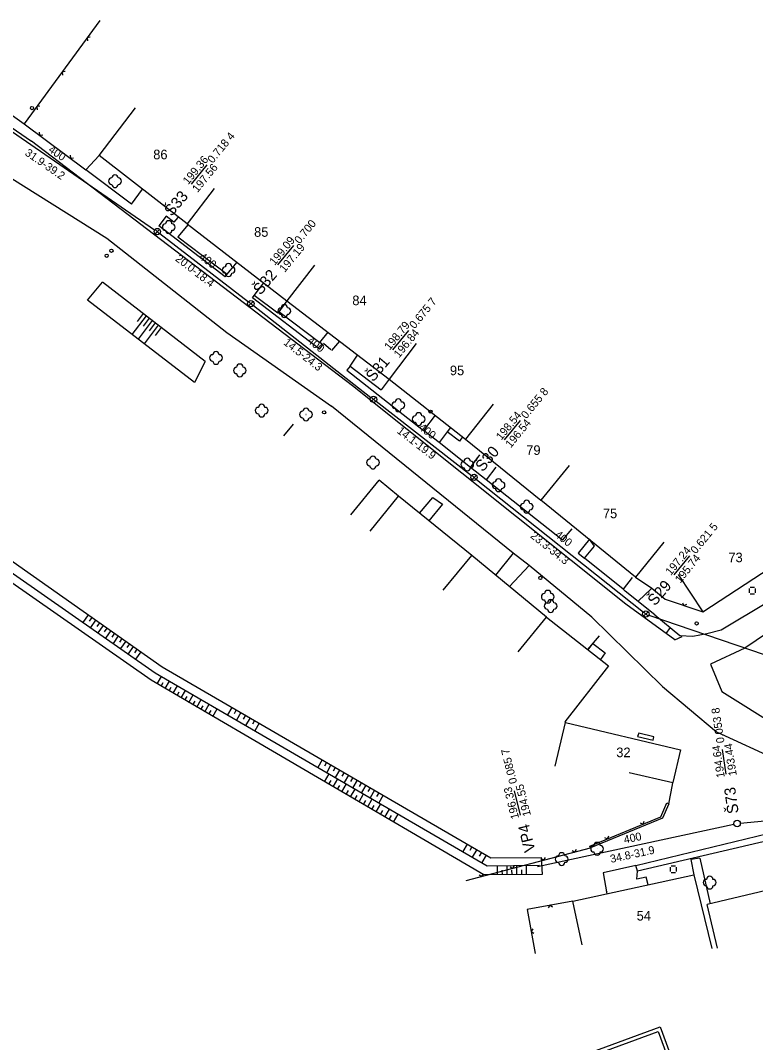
# Model space of a CAD drawing. Extents: x -574526 to -573537, y -1188297 to -1187280.
# Drawn here: x -574158.2 to -574043.3, y -1188086.8 to -1187927.2 of the extents above; entities that cross this region are included whole.
import ezdxf

# ---------------------------------------------------------------- set-up
doc = ezdxf.new("R2010")
doc.units = 0
for name, color, linetype in [('Vrstva 10', 7, 'Continuous'), ('Vrstva 12', 7, 'Continuous'), ('Vrstva 13', 7, 'Continuous'), ('Vrstva 14', 7, 'Continuous'), ('Vrstva 17', 7, 'Continuous'), ('Vrstva 18', 7, 'Continuous'), ('Vrstva 2', 7, 'Continuous'), ('Vrstva 21', 7, 'Continuous'), ('Vrstva 4', 7, 'Continuous'), ('Vrstva 41', 7, 'Continuous'), ('Vrstva 6', 7, 'Continuous'), ('Vrstva 7', 7, 'Continuous'), ('Vrstva 8', 7, 'Continuous'), ('Vrstva 9', 7, 'Continuous')]:
    doc.layers.add(name, color=color, linetype=linetype)

# ---------------------------------------------------------------- blocks, each defined once
blk = doc.blocks.new('3$130')
at = {"layer": 'Vrstva 8'}
blk.add_circle((0, 0), 0.001, dxfattribs=at)
for centre, start, end in [((-1, 0), 90, 270), ((0, 1), 0, 180), ((1, 0), 270, 90), ((0, -1), 180, 0)]:
    blk.add_arc(centre, 1, start, end, dxfattribs=at)
blk = doc.blocks.new('6$010')
at = {"layer": 'Vrstva 21'}
blk.add_circle((0, 0), 0.5, dxfattribs=at)
blk = doc.blocks.new('6$091')
at = {"layer": 'Vrstva 21'}
for p, q in [((-1, 0.7), (-1, -0.7)), ((0.7, 1), (-0.7, 1)), ((1, -0.7), (1, 0.7)), ((-0.7, -1), (0.7, -1))]:
    blk.add_line(p, q, dxfattribs=at)

msp = doc.modelspace()

# ---------------------------------------------------------------- linework, layer by layer
at = {"layer": 'Vrstva 10'}
for p, q in [((-574147.72, -1187970.91), (-574145.39, -1187968.11)), ((-574129.33, -1187980.45), (-574145.39, -1187968.11)), ((-574131.03, -1187983.73), (-574147.72, -1187970.91)), ((-574139.04, -1187972.99), (-574139.99, -1187974.22)), ((-574138.56, -1187973.35), (-574140.78, -1187976.24)), ((-574137.61, -1187974.09), (-574139.83, -1187976.97)), ((-574138.09, -1187973.72), (-574139.03, -1187974.95)), ((-574137.14, -1187974.45), (-574138.08, -1187975.68)), ((-574136.66, -1187974.82), (-574138.88, -1187977.7)), ((-574136.19, -1187975.18), (-574137.13, -1187976.41)), ((-574129.33, -1187980.45), (-574131.03, -1187983.73)), ((-574147.62, -1188020.02), (-574148.45, -1188021.21)), ((-574147.04, -1188020.44), (-574147.45, -1188021.03)), ((-574146.45, -1188020.85), (-574147.27, -1188022.03)), ((-574145.86, -1188021.26), (-574146.27, -1188021.85)), ((-574145.28, -1188021.68), (-574146.1, -1188022.85)), ((-574144.69, -1188022.09), (-574145.1, -1188022.68)), ((-574144.1, -1188022.5), (-574144.92, -1188023.67)), ((-574143.52, -1188022.92), (-574143.92, -1188023.5)), ((-574142.93, -1188023.33), (-574143.74, -1188024.49)), ((-574142.34, -1188023.74), (-574142.75, -1188024.32)), ((-574141.76, -1188024.16), (-574142.57, -1188025.31)), ((-574141.17, -1188024.57), (-574141.57, -1188025.15)), ((-574140.58, -1188024.98), (-574141.39, -1188026.14)), ((-574140, -1188025.39), (-574140.4, -1188025.97)), ((-574139.41, -1188025.81), (-574140.21, -1188026.96)), ((-574136.84, -1188030.82), (-574136.17, -1188029.66)), ((-574136.22, -1188031.18), (-574135.88, -1188030.6)), ((-574135.6, -1188031.55), (-574134.92, -1188030.38)), ((-574134.98, -1188031.91), (-574134.64, -1188031.33)), ((-574134.36, -1188032.27), (-574133.68, -1188031.11)), ((-574133.73, -1188032.64), (-574133.39, -1188032.05)), ((-574133.11, -1188033), (-574132.43, -1188031.83)), ((-574132.49, -1188033.36), (-574132.15, -1188032.78)), ((-574131.87, -1188033.73), (-574131.19, -1188032.55)), ((-574131.25, -1188034.09), (-574130.9, -1188033.5)), ((-574130.62, -1188034.45), (-574129.94, -1188033.28)), ((-574130, -1188034.82), (-574129.66, -1188034.23)), ((-574129.38, -1188035.18), (-574128.69, -1188034)), ((-574128.76, -1188035.54), (-574128.41, -1188034.95)), ((-574128.14, -1188035.91), (-574127.45, -1188034.72)), ((-574125.19, -1188034.48), (-574125.86, -1188035.64)), ((-574124.47, -1188034.89), (-574124.81, -1188035.48)), ((-574123.76, -1188035.31), (-574124.44, -1188036.47)), ((-574123.05, -1188035.72), (-574123.38, -1188036.3)), ((-574122.33, -1188036.14), (-574123.01, -1188037.3)), ((-574121.62, -1188036.55), (-574121.96, -1188037.13)), ((-574120.91, -1188036.97), (-574121.58, -1188038.13)), ((-574111.04, -1188042.69), (-574111.71, -1188043.86)), ((-574110.36, -1188043.09), (-574110.7, -1188043.67)), ((-574110.67, -1188046.1), (-574109.96, -1188044.88)), ((-574109.68, -1188043.48), (-574110.35, -1188044.65)), ((-574109, -1188043.88), (-574109.34, -1188044.46)), ((-574108.32, -1188044.27), (-574109, -1188045.44)), ((-574107.64, -1188044.67), (-574107.98, -1188045.25)), ((-574110, -1188046.5), (-574109.64, -1188045.88)), ((-574109.33, -1188046.89), (-574108.61, -1188045.66)), ((-574107.98, -1188047.68), (-574107.26, -1188046.44)), ((-574106.96, -1188045.06), (-574107.64, -1188046.22)), ((-574106.28, -1188045.45), (-574106.62, -1188046.04)), ((-574105.61, -1188045.85), (-574106.28, -1188047.01)), ((-574104.93, -1188046.24), (-574105.26, -1188046.82)), ((-574108.65, -1188047.28), (-574108.3, -1188046.67)), ((-574107.31, -1188048.07), (-574106.95, -1188047.45)), ((-574106.63, -1188048.46), (-574105.92, -1188047.23)), ((-574105.29, -1188049.25), (-574104.57, -1188048.01)), ((-574104.25, -1188046.64), (-574104.92, -1188047.8)), ((-574103.57, -1188047.03), (-574103.91, -1188047.61)), ((-574102.89, -1188047.42), (-574103.57, -1188048.59)), ((-574102.21, -1188047.82), (-574102.55, -1188048.4)), ((-574105.96, -1188048.86), (-574105.6, -1188048.24)), ((-574104.61, -1188049.64), (-574104.25, -1188049.02)), ((-574103.94, -1188050.03), (-574103.22, -1188048.79)), ((-574102.59, -1188050.82), (-574101.87, -1188049.57)), ((-574101.53, -1188048.21), (-574102.21, -1188049.38)), ((-574103.27, -1188050.43), (-574102.91, -1188049.81)), ((-574101.92, -1188051.21), (-574101.56, -1188050.59)), ((-574101.25, -1188051.61), (-574100.52, -1188050.36)), ((-574099.9, -1188052.39), (-574099.17, -1188051.14)), ((-574100.57, -1188052), (-574100.21, -1188051.37)), ((-574088.4, -1188055.84), (-574089.08, -1188057)), ((-574087.65, -1188056.27), (-574087.99, -1188056.85)), ((-574086.91, -1188056.7), (-574087.59, -1188057.87)), ((-574086.16, -1188057.13), (-574086.5, -1188057.72)), ((-574085.42, -1188057.57), (-574086.1, -1188058.73)), ((-574083.65, -1188060.61), (-574083.67, -1188059.21)), ((-574082.13, -1188060.6), (-574082.15, -1188059.18)), ((-574080.62, -1188060.6), (-574080.64, -1188059.16)), ((-574079.11, -1188060.59), (-574079.13, -1188059.14)), ((-574076.85, -1188057.9), (-574076.68, -1188060.58)), ((-574082.89, -1188060.61), (-574082.9, -1188059.9)), ((-574081.38, -1188060.6), (-574081.39, -1188059.89)), ((-574079.86, -1188060.59), (-574079.87, -1188059.87))]:
    msp.add_line(p, q, dxfattribs=at)
for points in [[(-574317.29, -1188004.39), (-574314.14, -1188013.05), (-574301.75, -1188030.62), (-574291.92, -1188042.55), (-574288.38, -1188041.78), (-574266.39, -1188025.47), (-574244.62, -1188011.25), (-574215.09, -1187994.87), (-574205.35, -1187992.52), (-574193.85, -1187992.52), (-574182.59, -1187996.03), (-574179.48, -1187997.59), (-574136.05, -1188028.17), (-574084.72, -1188057.97), (-574076.85, -1188057.9)], [(-574076.68, -1188060.58), (-574085.81, -1188060.62), (-574137.8, -1188030.26), (-574182.44, -1187999.09), (-574194.25, -1187995.12), (-574205.38, -1187995.31), (-574213.71, -1187997.65), (-574242.91, -1188013.72), (-574264.49, -1188027.8), (-574277.96, -1188037.93), (-574288.47, -1188045), (-574293.01, -1188045.4), (-574304.15, -1188032.01), (-574316.54, -1188013.81), (-574318.99, -1188004.72)], [(-574318.14, -1188004.55), (-574315.35, -1188013.5), (-574302.73, -1188031.74), (-574292.54, -1188043.84), (-574288.81, -1188043.39), (-574285.58, -1188041.49), (-574264.64, -1188026.29), (-574243.98, -1188012.52), (-574214.39, -1187996.33), (-574205.28, -1187993.91), (-574194.11, -1187993.91), (-574181.46, -1187998.19), (-574137.17, -1188029.08), (-574085.25, -1188059.23), (-574077.09, -1188059.12)]]:
    msp.add_lwpolyline(points, dxfattribs=at)
at = {"layer": 'Vrstva 13'}
for p, q in [((-574131.49, -1187952.81), (-574129.01, -1187949.79)), ((-574117.96, -1187965.4), (-574115.49, -1187962.38)), ((-574100, -1187978.65), (-574097.52, -1187975.64)), ((-574082.55, -1187992.71), (-574080.07, -1187989.69)), ((-574056.06, -1188013.81), (-574053.58, -1188010.8)), ((-574047.91, -1188044.92), (-574048.5, -1188041.06)), ((-574080.08, -1188051.29), (-574081.02, -1188047.5))]:
    msp.add_line(p, q, dxfattribs=at)
at = {"layer": 'Vrstva 17'}
for p, q in [((-574137.17, -1187960.55), (-574136.46, -1187959.84)), ((-574137.17, -1187959.84), (-574136.46, -1187960.55)), ((-574122.55, -1187971.8), (-574121.84, -1187971.09)), ((-574122.55, -1187971.09), (-574121.84, -1187971.8)), ((-574103.39, -1187986.74), (-574102.68, -1187986.03)), ((-574103.39, -1187986.03), (-574102.68, -1187986.74)), ((-574087.67, -1187998.93), (-574086.96, -1187998.22)), ((-574087.67, -1187998.22), (-574086.96, -1187998.93)), ((-574060.82, -1188020.26), (-574060.11, -1188019.56)), ((-574060.82, -1188019.56), (-574060.11, -1188020.26))]:
    msp.add_line(p, q, dxfattribs=at)
at = {"layer": 'Vrstva 2'}
for p, q in [((-574168.68, -1187938.27), (-574137.23, -1187959.91)), ((-574136.42, -1187960.5), (-574122.59, -1187971.14)), ((-574121.8, -1187971.75), (-574103.43, -1187986.08)), ((-574102.64, -1187986.69), (-574087.71, -1187998.27)), ((-574086.93, -1187998.89), (-574060.86, -1188019.6)), ((-574059.99, -1188020.07), (-573995.71, -1188042.01)), ((-574045.71, -1188052.57), (-574001.26, -1188048.17)), ((-574077.38, -1188059.33), (-574046.7, -1188052.73))]:
    msp.add_line(p, q, dxfattribs=at)
at = {"layer": 'Vrstva 41'}
for points in [[(-574145.41, -1188116.41), (-574058.21, -1188084.39), (-574036.76, -1188142.83), (-574123.95, -1188174.84), (-574145.41, -1188116.41)], [(-574144.69, -1188116.76), (-574058.53, -1188085.12), (-574037.46, -1188142.5), (-574123.63, -1188174.14), (-574144.69, -1188116.76)]]:
    msp.add_lwpolyline(points, close=True, dxfattribs=at)
at = {"layer": 'Vrstva 6'}
for p, q in [((-574145.81, -1187927.22), (-574157.62, -1187943.36)), ((-574157.62, -1187943.36), (-574147.98, -1187950.54)), ((-574147.98, -1187950.54), (-574145.91, -1187948.33)), ((-574131.97, -1187959.09), (-574133.6, -1187961)), ((-574133.6, -1187961), (-574125.9, -1187966.86)), ((-574125.9, -1187966.86), (-574124.34, -1187964.98)), ((-574121.66, -1187970.17), (-574120.16, -1187968.2)), ((-574118, -1187972.95), (-574121.66, -1187970.17)), ((-574116.55, -1187970.99), (-574118, -1187972.95)), ((-574117.83, -1187972.65), (-574111.43, -1187977.52)), ((-574111.43, -1187977.52), (-574110.13, -1187975.91)), ((-574110.93, -1187977.85), (-574111.43, -1187977.52)), ((-574109.56, -1187978.76), (-574108.29, -1187977.32)), ((-574106.66, -1187981.23), (-574105.54, -1187979.51)), ((-574106.66, -1187981.23), (-574101.81, -1187984.92)), ((-574100.6, -1187983.21), (-574101.81, -1187984.92)), ((-574062.08, -1188014.13), (-574059.55, -1188015.88)), ((-574061.6, -1188017.83), (-574059.67, -1188016.05)), ((-574059.67, -1188016.05), (-574059.55, -1188015.88)), ((-574059.55, -1188015.88), (-574057.44, -1188017.61)), ((-574057.44, -1188017.61), (-574051.58, -1188019.59)), ((-574048.71, -1188022.38), (-574041.33, -1188017.96)), ((-574050.93, -1188022.95), (-574048.71, -1188022.38)), ((-574069.55, -1188025.45), (-574067.74, -1188023.32)), ((-574055.15, -1188023.24), (-574053.11, -1188023.37)), ((-574053.11, -1188023.37), (-574050.93, -1188022.95)), ((-574069.48, -1188025.51), (-574068.75, -1188024.52)), ((-574068.75, -1188024.52), (-574066.81, -1188025.96)), ((-574066.81, -1188025.96), (-574067.56, -1188027.02)), ((-574061.58, -1188038.53), (-574061.76, -1188039.04)), ((-574059.21, -1188039.07), (-574061.58, -1188038.53)), ((-574061.76, -1188039.04), (-574059.33, -1188039.59)), ((-574059.33, -1188039.59), (-574059.21, -1188039.07)), ((-574056.31, -1188046.58), (-574056.25, -1188046.23)), ((-574056.9, -1188049.52), (-574056.31, -1188046.58)), ((-574058.12, -1188051.57), (-574057.17, -1188049.4)), ((-574056.9, -1188049.52), (-574057.89, -1188051.8)), ((-574057.17, -1188049.4), (-574056.9, -1188049.52)), ((-574069.24, -1188056.16), (-574058.12, -1188051.57)), ((-574057.89, -1188051.8), (-574069.13, -1188056.44)), ((-574088.53, -1188061.53), (-574069.13, -1188056.44)), ((-574069.13, -1188056.44), (-574069.24, -1188056.16)), ((-574071.9, -1188064.73), (-574079.03, -1188066.03)), ((-574079.03, -1188066.03), (-574077.78, -1188072.91))]:
    msp.add_line(p, q, dxfattribs=at)
for points in [[(-574147.29, -1187929.83), (-574147.78, -1187929.91), (-574147.7, -1187930.4)], [(-574151.23, -1187935.21), (-574151.71, -1187935.29), (-574151.64, -1187935.78)], [(-574155.16, -1187940.59), (-574155.65, -1187940.67), (-574155.58, -1187941.16)], [(-574155.28, -1187944.67), (-574155.21, -1187945.16), (-574154.72, -1187945.08)], [(-574150.46, -1187948.26), (-574150.39, -1187948.75), (-574149.9, -1187948.67)], [(-574054.73, -1188018.16), (-574054.51, -1188018.6), (-574054.07, -1188018.38)], [(-574061.36, -1188052.53), (-574060.9, -1188052.72), (-574060.71, -1188052.26)], [(-574066.92, -1188054.82), (-574066.46, -1188055.01), (-574066.27, -1188054.56)], [(-574071.98, -1188056.83), (-574071.56, -1188057.08), (-574071.31, -1188056.65)], [(-574081.68, -1188059.37), (-574081.26, -1188059.62), (-574081.01, -1188059.19)], [(-574076.83, -1188058.1), (-574076.41, -1188058.35), (-574076.16, -1188057.92)], [(-574086.53, -1188060.64), (-574086.1, -1188060.89), (-574085.86, -1188060.47)], [(-574075.06, -1188065.66), (-574075.47, -1188065.38), (-574075.75, -1188065.78)], [(-574078.12, -1188069.06), (-574078.41, -1188069.47), (-574078, -1188069.75)]]:
    msp.add_lwpolyline(points, dxfattribs=at)
at = {"layer": 'Vrstva 7'}
for p, q in [((-574145.91, -1187948.33), (-574140.25, -1187940.89)), ((-574132.17, -1187958.99), (-574145.91, -1187948.33)), ((-574127.91, -1187953.44), (-574132.17, -1187958.99)), ((-574132.17, -1187958.99), (-574116.55, -1187970.99)), ((-574112.27, -1187965.45), (-574116.55, -1187970.99)), ((-574116.55, -1187970.99), (-574100.6, -1187983.21)), ((-574096.34, -1187977.65), (-574100.6, -1187983.21)), ((-574100.6, -1187983.21), (-574088.64, -1187992.62)), ((-574084.31, -1187987.12), (-574088.64, -1187992.62)), ((-574117.04, -1187992.1), (-574115.51, -1187990.24)), ((-574088.64, -1187992.62), (-574076.86, -1188002.14)), ((-574072.46, -1187996.7), (-574076.86, -1188002.14)), ((-574106.6, -1188004.43), (-574102.15, -1187999.03)), ((-574099.13, -1188001.52), (-574102.15, -1187999.03)), ((-574103.53, -1188006.97), (-574099.13, -1188001.52)), ((-574087.68, -1188010.76), (-574099.13, -1188001.52)), ((-574062.08, -1188014.13), (-574076.86, -1188002.14)), ((-574057.67, -1188008.69), (-574062.08, -1188014.13)), ((-574092.13, -1188016.17), (-574087.68, -1188010.76)), ((-574075.99, -1188020.38), (-574087.68, -1188010.76)), ((-574051.58, -1188019.59), (-574038.35, -1188010.94)), ((-574055.41, -1188013.73), (-574051.58, -1188019.59)), ((-574080.44, -1188025.79), (-574075.99, -1188020.38)), ((-574075.99, -1188020.38), (-574066.3, -1188028.01)), ((-574066.3, -1188028.01), (-574073.15, -1188036.73)), ((-574074.62, -1188043.67), (-574073.01, -1188036.86)), ((-574073.15, -1188036.73), (-574073.01, -1188036.86)), ((-574073.01, -1188036.86), (-574055.07, -1188041.09)), ((-574055.07, -1188041.09), (-574056.25, -1188046.23)), ((-574063.07, -1188044.66), (-574056.25, -1188046.23)), ((-574056.25, -1188046.23), (-574056.22, -1188046.1)), ((-574071.9, -1188064.73), (-574052.98, -1188060.65)), ((-574052.98, -1188060.65), (-574050.17, -1188072.11)), ((-574030.86, -1188060.49), (-574050.87, -1188065.26)), ((-574070.42, -1188071.57), (-574071.9, -1188064.73)), ((-574049.25, -1188072.07), (-574050.87, -1188065.26))]:
    msp.add_line(p, q, dxfattribs=at)
at = {"layer": 'Vrstva 8'}
for centre in [(-574136.82, -1187960.19), (-574122.2, -1187971.44), (-574103.03, -1187986.39), (-574087.32, -1187998.57), (-574060.47, -1188019.91), (-574046.21, -1188052.62)]:
    msp.add_circle(centre, 0.5, dxfattribs=at)
at = {"layer": 'Vrstva 9'}
for p, q in [((-574179.15, -1187939.7), (-574144.7, -1187961.2)), ((-574106.32, -1187984.27), (-574156.49, -1187946.06)), ((-574140.84, -1187955.89), (-574147.98, -1187950.54)), ((-574140.84, -1187955.89), (-574139.14, -1187953.58)), ((-574135.43, -1187957.8), (-574136.57, -1187959.27)), ((-574134.25, -1187958.74), (-574135.43, -1187957.8)), ((-574133.62, -1187957.97), (-574134.25, -1187958.74)), ((-574126.2, -1187967.25), (-574136.57, -1187959.27)), ((-574144.7, -1187961.2), (-574125.95, -1187975.97)), ((-574126.2, -1187967.25), (-574125.9, -1187966.86)), ((-574121.93, -1187970.53), (-574121.66, -1187970.17)), ((-574111.49, -1187978.55), (-574121.93, -1187970.53)), ((-574125.95, -1187975.97), (-574109.61, -1187987.44)), ((-574111.49, -1187978.55), (-574110.93, -1187977.85)), ((-574109.71, -1187978.63), (-574110.82, -1187977.68)), ((-574106.66, -1187981.23), (-574107.2, -1187981.81)), ((-574107.2, -1187981.81), (-574095.23, -1187991.23)), ((-574063.62, -1188018.37), (-574106.32, -1187984.27)), ((-574081.22, -1188010.4), (-574109.61, -1187987.44)), ((-574093.42, -1187988.86), (-574095.23, -1187991.23)), ((-574092.77, -1187993.11), (-574095.23, -1187991.23)), ((-574091.52, -1187991.48), (-574092.77, -1187993.11)), ((-574090.99, -1187990.77), (-574091.52, -1187991.48)), ((-574089.6, -1187992.92), (-574091.52, -1187991.48)), ((-574089.1, -1187992.26), (-574089.6, -1187992.92)), ((-574087.88, -1187997.01), (-574092.77, -1187993.11)), ((-574087.88, -1187997.01), (-574086.43, -1187995.07)), ((-574085.44, -1187998.97), (-574087.88, -1187997.01)), ((-574083.93, -1187996.98), (-574085.44, -1187998.97)), ((-574073.49, -1188008.37), (-574085.44, -1187998.97)), ((-574095.85, -1188004.17), (-574093.74, -1188001.71)), ((-574093.74, -1188001.71), (-574092.24, -1188002.76)), ((-574092.24, -1188002.76), (-574094.4, -1188005.33)), ((-574073.49, -1188008.37), (-574071.99, -1188006.62)), ((-574069.3, -1188008.24), (-574071.04, -1188010.41)), ((-574068.49, -1188009.3), (-574069.3, -1188008.24)), ((-574070.06, -1188011.2), (-574068.49, -1188009.3)), ((-574081.22, -1188010.4), (-574083.95, -1188013.83)), ((-574078.7, -1188012.32), (-574081.22, -1188010.4)), ((-574071.04, -1188010.41), (-574070.06, -1188011.2)), ((-574064.02, -1188016.01), (-574070.06, -1188011.2)), ((-574078.7, -1188012.32), (-574081.76, -1188015.63)), ((-574068.93, -1188020.41), (-574078.7, -1188012.32)), ((-574062.6, -1188014.18), (-574064.02, -1188016.01)), ((-574029.15, -1188014.48), (-574045, -1188025.26)), ((-574063.68, -1188016.33), (-574064.02, -1188016.01)), ((-574059.09, -1188020.03), (-574063.68, -1188016.33)), ((-574055.96, -1188023.92), (-574063.62, -1188018.37)), ((-574068.93, -1188020.41), (-574057.85, -1188031.23)), ((-574059.09, -1188020.03), (-574055.15, -1188023.24)), ((-574056.69, -1188022.03), (-574057.34, -1188022.93)), ((-574055.96, -1188023.92), (-574054.82, -1188023.4)), ((-574054.82, -1188023.4), (-574055.15, -1188023.24)), ((-574045, -1188025.26), (-574050.37, -1188027.73)), ((-574050.37, -1188027.73), (-574048.59, -1188031.99)), ((-574057.85, -1188031.23), (-574049.44, -1188038.29)), ((-574048.59, -1188031.99), (-574037.47, -1188039.02)), ((-574049.44, -1188038.29), (-574035.74, -1188044.64)), ((-574062.02, -1188059.15), (-574037.32, -1188053.2)), ((-574037.05, -1188054.27), (-574061.78, -1188060.07)), ((-574062.02, -1188059.15), (-574067.12, -1188060.31)), ((-574061.78, -1188060.07), (-574062.02, -1188059.15)), ((-574052.06, -1188058.02), (-574053.44, -1188058.24)), ((-574053.44, -1188058.24), (-574052.98, -1188060.65)), ((-574052.06, -1188058.02), (-574050.44, -1188065.16)), ((-574067.12, -1188060.31), (-574066.58, -1188063.58)), ((-574061.9, -1188061.33), (-574061.78, -1188060.07)), ((-574060.42, -1188060.98), (-574061.9, -1188061.33)), ((-574060.11, -1188062.19), (-574060.42, -1188060.98)), ((-574066.66, -1188063.11), (-574066.52, -1188063.22))]:
    msp.add_line(p, q, dxfattribs=at)
for points in [[(-574204.72, -1187930.94), (-574193.38, -1187930.38), (-574183.41, -1187931.57), (-574173.56, -1187934.41), (-574164.08, -1187938.81), (-574157.62, -1187943.36)], [(-574201.94, -1187932.17), (-574192.95, -1187931.99), (-574183.53, -1187933.22), (-574174.82, -1187935.67), (-574165.25, -1187940.1), (-574156.49, -1187946.06)]]:
    msp.add_lwpolyline(points, dxfattribs=at)

# ---------------------------------------------------------------- block references
at = {"layer": 'Vrstva 21', "xscale": 0.5, "yscale": 0.5}
for name, p in [('6$010', (-574156.4, -1187940.91)), ('6$010', (-574143.99, -1187963.18)), ('6$010', (-574144.73, -1187963.97)), ('6$010', (-574110.75, -1187988.42)), ('6$010', (-574094.12, -1187988.3)), ('6$010', (-574076.96, -1188014.27)), ('6$091', (-574043.83, -1188016.25)), ('6$010', (-574052.54, -1188021.38)), ('6$091', (-574056.17, -1188059.76))]:
    msp.add_blockref(name, p, dxfattribs=at)
at = {"layer": 'Vrstva 4', "xscale": 0.5, "yscale": 0.5}
for p in [(-574143.43, -1187952.32), (-574135.03, -1187959.49), (-574125.68, -1187966.19), (-574116.97, -1187972.6), (-574127.64, -1187979.91), (-574123.92, -1187981.87), (-574120.51, -1187988.14), (-574099.15, -1187987.3), (-574113.58, -1187988.75), (-574095.97, -1187989.47), (-574103.12, -1187996.25), (-574088.38, -1187996.56), (-574083.49, -1187999.79), (-574079.1, -1188003.14), (-574075.8, -1188017.21), (-574075.34, -1188018.66), (-574068.09, -1188056.56), (-574073.63, -1188058.18), (-574050.49, -1188061.84)]:
    msp.add_blockref('3$130', p, dxfattribs=at)

# ---------------------------------------------------------------- texts
at = {"layer": 'Vrstva 12'}
for s, p in [('86', (-574137.45, -1187948.9)), ('85', (-574121.69, -1187961)), ('84', (-574106.34, -1187971.68)), ('95', (-574091.09, -1187982.62)), ('79', (-574079.16, -1187995.06)), ('75', (-574067.18, -1188004.95)), ('73', (-574047.57, -1188011.82)), ('32', (-574065.09, -1188042.26)), ('54', (-574061.91, -1188067.77))]:
    msp.add_text(s, height=1.5, dxfattribs=at).set_placement(p)
at = {"layer": 'Vrstva 13'}
for s, height, rotation, p in [('0.718 4', 1.25, 50.604, (-574128.15, -1187949.62)), ('199.36', 1.25, 50.604, (-574131.99, -1187952.95)), ('197.56', 1.25, 50.604, (-574130.52, -1187954.17)), ('0.700', 1.25, 50.604, (-574114.56, -1187962.21)), ('199.09', 1.25, 50.604, (-574118.47, -1187965.55)), ('197.19', 1.25, 50.604, (-574116.9, -1187966.64)), ('0.675 7', 1.25, 50.604, (-574096.6, -1187975.46)), ('198.79', 1.25, 50.604, (-574100.51, -1187978.8)), ('196.84', 1.25, 50.604, (-574099.03, -1187980)), ('0.655 8', 1.25, 50.604, (-574079.15, -1187989.52)), ('198.54', 1.25, 50.604, (-574083.06, -1187992.86)), ('196.54', 1.25, 50.604, (-574081.58, -1187994.06)), ('0.621 5', 1.25, 50.604, (-574052.66, -1188010.62)), ('197.24', 1.25, 50.604, (-574056.57, -1188013.97)), ('195.74', 1.25, 50.604, (-574055.09, -1188015.18)), ('0.053 8', 1.25, 98.7261, (-574048.17, -1188039.97)), ('193.44', 1.25, 98.7261, (-574046.25, -1188045.09)), ('0.085 7', 1.249, 103.8894, (-574080.57, -1188046.25)), ('194.64', 1.25, 98.7261, (-574048.13, -1188045.39)), ('194.55', 1.249, 103.8894, (-574078.41, -1188051.33)), ('196.33', 1.249, 103.8894, (-574080.27, -1188051.76))]:
    msp.add_text(s, height=height, rotation=rotation, dxfattribs=at).set_placement(p)
at = {"layer": 'Vrstva 14'}
for s, rotation, p in [('31.9-39.2', 325.4703, (-574157.61, -1187948.17)), ('400', 325.4703, (-574153.95, -1187947.65)), ('20.0-18.4', 322.4236, (-574134.1, -1187964.65)), ('400', 322.4236, (-574130.39, -1187964.35)), ('14.5-24.3', 322.0565, (-574117.2, -1187977.72)), ('400', 322.0565, (-574113.49, -1187977.44)), ('400', 322.2014, (-574096.09, -1187990.98)), ('14.1-19.9', 322.2014, (-574099.46, -1187991.53)), ('23.3-34.3', 321.5321, (-574078.62, -1188007.88)), ('400', 321.5321, (-574074.79, -1188007.73)), ('400', 12.1363, (-574063.78, -1188055.76)), ('34.8-31.9', 12.1363, (-574065.91, -1188058.78))]:
    msp.add_text(s, height=1.25, rotation=rotation, dxfattribs=at).set_placement(p)
at = {"layer": 'Vrstva 18'}
for s, height, rotation, p in [('Š33', 1.75, 49.6819, (-574134.57, -1187957.92)), ('Š32', 1.75, 49.6819, (-574120.69, -1187970.21)), ('Š31', 1.75, 49.6819, (-574103.08, -1187983.76)), ('Š30', 1.75, 49.6819, (-574085.96, -1187997.8)), ('Š29', 1.75, 49.6819, (-574059.04, -1188018.74)), ('Š73', 1.75, 97.804, (-574045.96, -1188050.97)), ('VP4', 1.749, 103.8894, (-574077.72, -1188056.86))]:
    msp.add_text(s, height=height, rotation=rotation, dxfattribs=at).set_placement(p)

doc.saveas('drawing.dxf')
